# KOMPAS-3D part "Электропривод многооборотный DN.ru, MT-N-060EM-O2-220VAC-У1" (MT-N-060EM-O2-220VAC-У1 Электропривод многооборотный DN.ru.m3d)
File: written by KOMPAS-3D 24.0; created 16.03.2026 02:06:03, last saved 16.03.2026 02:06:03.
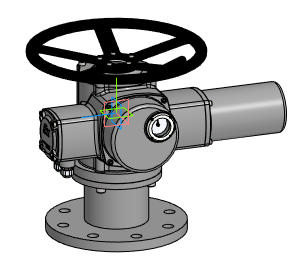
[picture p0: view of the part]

Document properties: Автор: DN.RU; Полное имя файла: D:\PROJECT CAD\DN.RU\...193.(ACTUALE) MT-N-xEM-O2-x-У1 Электропривод многооборотный DN.ru\MT-N-060EM-O2-220VAC-У1\MT-N-060EM-O2-220VAC-У1 Электропривод многооборотный DN.ru.m3d

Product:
- Body: Твердое тело1  | qty 1
    Масса: 81.739772
- Body: Твердое тело1  | qty 1
    Масса: 1.394298
- Part/product: Электропривод многооборотный DN.ru  | designation MT-N-060EM-O2-220VAC-У1
    Масса: 25
    Раздел спецификации: Прочие изделия
    Комментарий: D300-04897
    Примечание: D300-04897
    additional columns: Типовые

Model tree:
1. Твердое тело1  (labels: Твердое тело1)

Expressions: MT-N-060EM-O2-220VAC-У1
